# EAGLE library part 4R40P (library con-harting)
CONNECTOR
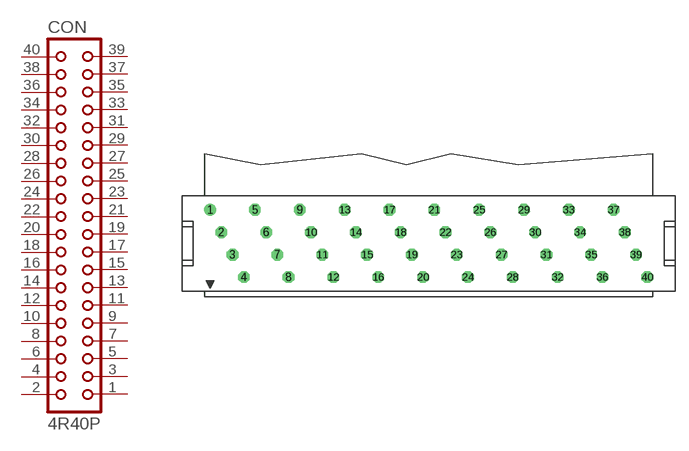
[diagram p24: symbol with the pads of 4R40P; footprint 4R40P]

Designator prefix CON

## 4R40P (OC_FARNELL: unknown; OC_NEWARK: unknown)  [4R40P]
1  1  pas
2  2  pas
3  3  pas
4  4  pas
5  5  pas
6  6  pas
7  7  pas
8  8  pas
9  9  pas
10  10  pas
11  11  pas
12  12  pas
13  13  pas
14  14  pas
15  15  pas
16  16  pas
17  17  pas
18  18  pas
19  19  pas
20  20  pas
21  21  pas
22  22  pas
23  23  pas
24  24  pas
25  25  pas
26  26  pas
27  27  pas
28  28  pas
29  29  pas
30  30  pas
31  31  pas
32  32  pas
33  33  pas
34  34  pas
35  35  pas
36  36  pas
37  37  pas
38  38  pas
39  39  pas
40  40  pas

## Footprint 4R40P (pad centres in mm)
CONNECTOR
drill 0.813 round: 1 -24.765,3.81
drill 0.813 octagon: 2 -23.495,1.27; 3 -22.225,-1.27; 4 -20.955,-3.81; 5 -19.685,3.81; 6 -18.415,1.27; 7 -17.145,-1.27; 8 -15.875,-3.81; 9 -14.605,3.81; 10 -13.335,1.27; 11 -12.065,-1.27; 12 -10.795,-3.81; 13 -9.525,3.81; 14 -8.255,1.27; 15 -6.985,-1.27; 16 -5.715,-3.81; 17 -4.445,3.81; 18 -3.175,1.27; 19 -1.905,-1.27; 20 -0.635,-3.81; 21 0.635,3.81; 22 1.905,1.27; 23 3.175,-1.27; 24 4.445,-3.81; 25 5.715,3.81; 26 6.985,1.27; 27 8.255,-1.27; 28 9.525,-3.81; 29 10.795,3.81; 30 12.065,1.27; 31 13.335,-1.27; 32 14.605,-3.81; 33 15.875,3.81; 34 17.145,1.27; 35 18.415,-1.27; 36 19.685,-3.81; 37 20.955,3.81; 38 22.225,1.27; 39 23.495,-1.27; 40 24.765,-3.81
